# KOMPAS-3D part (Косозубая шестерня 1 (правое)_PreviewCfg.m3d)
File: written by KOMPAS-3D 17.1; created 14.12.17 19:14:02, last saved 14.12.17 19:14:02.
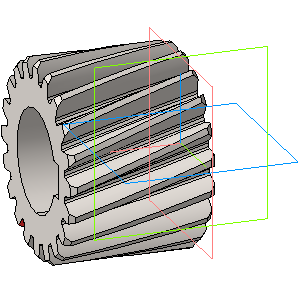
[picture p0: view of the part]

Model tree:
1. Операция без истории:1  (labels: Косозубая шестерня 1 (правое)_PreviewCfg)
